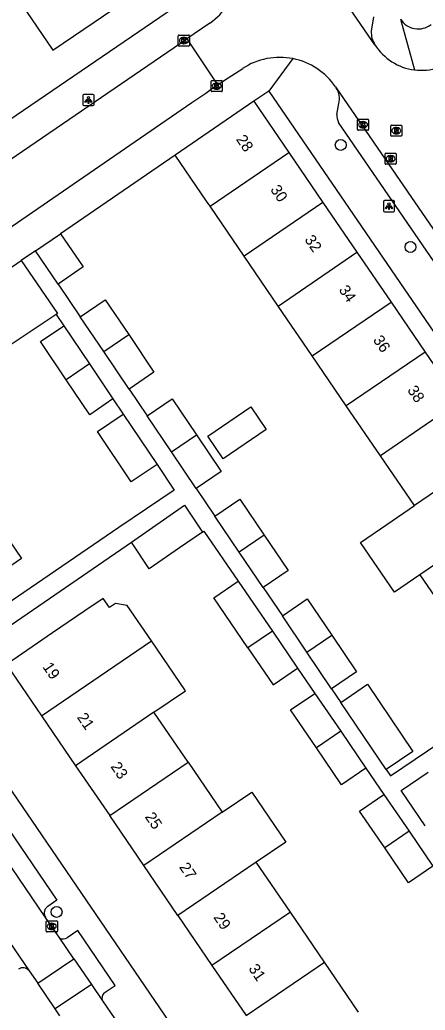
# Model space of a CAD drawing. Extents: x 157466 to 158888, y 383063 to 384677.
# Drawn here: x 158228.2 to 158264.6, y 383822.7 to 383911.7 of the extents above; entities that cross this region are included whole.
import ezdxf

# ---------------------------------------------------------------- set-up
doc = ezdxf.new("R2010")
doc.units = 0
for name, color, linetype in [('IMGEO_Boom', 7, 'Continuous'), ('IMGEO_Kolk', 7, 'Continuous'), ('IMGEO_Lichtpunt', 7, 'Continuous'), ('IMGEO_Muur', 7, 'Continuous'), ('IMGEO_Pand', 7, 'Continuous'), ('IMGEO_Pand_nummerreeks', 7, 'Continuous'), ('IMGEO_Rijbaan_lokaal_open', 7, 'Continuous'), ('IMGEO_Rioolput', 7, 'Continuous'), ('IMGEO_Voetpad_open', 7, 'Continuous')]:
    doc.layers.add(name, color=color, linetype=linetype)

msp = doc.modelspace()

# ---------------------------------------------------------------- linework, layer by layer
at = {"layer": 'IMGEO_Boom'}
for centre in [(158257.057, 383900.449), (158263.312, 383891.278), (158231.547, 383831.557)]:
    msp.add_circle(centre, 0.489, dxfattribs=at)
at = {"layer": 'IMGEO_Kolk'}
for p, q in [((158242.465, 383909.389), (158242.465, 383910.241)), ((158242.54, 383910.315), (158243.392, 383910.315)), ((158242.953, 383910.095), (158242.978, 383910.095)), ((158243.466, 383910.241), (158243.466, 383909.389)), ((158243.392, 383909.315), (158242.54, 383909.315)), ((158242.976, 383909.535), (158242.951, 383909.535)), ((158245.42, 383905.308), (158245.42, 383906.16)), ((158245.495, 383906.234), (158246.347, 383906.234)), ((158246.421, 383906.16), (158246.421, 383905.308)), ((158246.347, 383905.234), (158245.495, 383905.234)), ((158245.931, 383905.454), (158245.906, 383905.454)), ((158245.908, 383906.014), (158245.933, 383906.014)), ((158258.559, 383901.837), (158258.559, 383902.689)), ((158258.634, 383902.763), (158259.486, 383902.763)), ((158259.047, 383902.543), (158259.072, 383902.543)), ((158259.56, 383902.689), (158259.56, 383901.837)), ((158259.486, 383901.763), (158258.634, 383901.763)), ((158259.07, 383901.983), (158259.045, 383901.983)), ((158230.613, 383829.835), (158230.613, 383830.687)), ((158230.688, 383830.761), (158231.54, 383830.761)), ((158231.101, 383830.541), (158231.126, 383830.541)), ((158231.614, 383830.687), (158231.614, 383829.835)), ((158231.54, 383829.761), (158230.688, 383829.761)), ((158231.124, 383829.981), (158231.099, 383829.981))]:
    msp.add_line(p, q, dxfattribs=at)
for points in [[(158242.465, 383909.389), (158242.465, 383910.241)], [(158242.54, 383910.315), (158243.392, 383910.315)], [(158242.786, 383910.015), (158242.909, 383910.015), (158242.909, 383909.864), (158243.039, 383910.015), (158243.203, 383910.015), (158243.057, 383909.864), (158243.21, 383909.615), (158243.058, 383909.615), (158242.973, 383909.779), (158242.909, 383909.712), (158242.909, 383909.615), (158242.786, 383909.615), (158242.786, 383910.015)], [(158243.466, 383910.241), (158243.466, 383909.389)], [(158243.392, 383909.315), (158242.54, 383909.315)], [(158245.42, 383905.308), (158245.42, 383906.16)], [(158245.495, 383906.234), (158246.347, 383906.234)], [(158246.421, 383906.16), (158246.421, 383905.308)], [(158246.347, 383905.234), (158245.495, 383905.234)], [(158245.741, 383905.934), (158245.864, 383905.934), (158245.864, 383905.783), (158245.994, 383905.934), (158246.158, 383905.934), (158246.012, 383905.783), (158246.165, 383905.534), (158246.013, 383905.534), (158245.928, 383905.698), (158245.864, 383905.631), (158245.864, 383905.534), (158245.741, 383905.534), (158245.741, 383905.934)], [(158258.559, 383901.837), (158258.559, 383902.689)], [(158258.634, 383902.763), (158259.486, 383902.763)], [(158259.56, 383902.689), (158259.56, 383901.837)], [(158259.486, 383901.763), (158258.634, 383901.763)], [(158258.88, 383902.463), (158259.003, 383902.463), (158259.003, 383902.312), (158259.133, 383902.463), (158259.297, 383902.463), (158259.151, 383902.312), (158259.304, 383902.063), (158259.152, 383902.063), (158259.067, 383902.227), (158259.003, 383902.16), (158259.003, 383902.063), (158258.88, 383902.063), (158258.88, 383902.463)], [(158230.613, 383829.835), (158230.613, 383830.687)], [(158230.688, 383830.761), (158231.54, 383830.761)], [(158230.934, 383830.461), (158231.057, 383830.461), (158231.057, 383830.31), (158231.187, 383830.461), (158231.351, 383830.461), (158231.205, 383830.31), (158231.358, 383830.061), (158231.206, 383830.061), (158231.121, 383830.225), (158231.057, 383830.158), (158231.057, 383830.061), (158230.934, 383830.061), (158230.934, 383830.461)], [(158231.614, 383830.687), (158231.614, 383829.835)], [(158231.54, 383829.761), (158230.688, 383829.761)]]:
    msp.add_lwpolyline(points, dxfattribs=at)
for centre, start, end in [((158242.542, 383910.239), 91.55205, 178.44795), ((158242.542, 383910.239), 91.55205, 178.44795), ((158243.39, 383910.239), 1.55205, 88.44795), ((158243.39, 383910.239), 1.55205, 88.44795), ((158242.542, 383909.391), 181.55205, 268.44795), ((158242.542, 383909.391), 181.55205, 268.44795), ((158243.39, 383909.391), 271.55205, 358.44795), ((158243.39, 383909.391), 271.55205, 358.44795), ((158245.497, 383906.158), 91.55205, 178.44795), ((158245.497, 383906.158), 91.55205, 178.44795), ((158246.345, 383906.158), 1.55205, 88.44795), ((158246.345, 383906.158), 1.55205, 88.44795), ((158245.497, 383905.31), 181.55205, 268.44795), ((158245.497, 383905.31), 181.55205, 268.44795), ((158246.345, 383905.31), 271.55205, 358.44795), ((158246.345, 383905.31), 271.55205, 358.44795), ((158258.636, 383902.687), 91.55205, 178.44795), ((158258.636, 383902.687), 91.55205, 178.44795), ((158259.484, 383902.687), 1.55205, 88.44795), ((158259.484, 383902.687), 1.55205, 88.44795), ((158258.636, 383901.839), 181.55205, 268.44795), ((158258.636, 383901.839), 181.55205, 268.44795), ((158259.484, 383901.839), 271.55205, 358.44795), ((158259.484, 383901.839), 271.55205, 358.44795), ((158230.69, 383830.685), 91.55205, 178.44795), ((158230.69, 383830.685), 91.55205, 178.44795), ((158231.538, 383830.685), 1.55205, 88.44795), ((158231.538, 383830.685), 1.55205, 88.44795), ((158230.69, 383829.837), 181.55205, 268.44795), ((158230.69, 383829.837), 181.55205, 268.44795), ((158231.538, 383829.837), 271.55205, 358.44795), ((158231.538, 383829.837), 271.55205, 358.44795)]:
    msp.add_arc(centre, 0.0765, start, end, dxfattribs=at)
for centre, major_axis, ratio, start_param, end_param in [((158242.952, 383909.815), (-0.387, 0.002), 0.722429, 4.712389, 7.853982), ((158242.977, 383909.815), (-0.39, 0.002), 0.717154, 1.570796, 4.712389), ((158245.907, 383905.734), (-0.387, 0.002), 0.722429, 4.712389, 7.853982), ((158245.932, 383905.734), (-0.39, 0.002), 0.717154, 1.570796, 4.712389), ((158259.046, 383902.263), (-0.387, 0.002), 0.722429, 4.712389, 7.853982), ((158259.071, 383902.263), (-0.39, 0.002), 0.717154, 1.570796, 4.712389), ((158231.1, 383830.261), (-0.387, 0.002), 0.722429, 4.712389, 7.853982), ((158231.125, 383830.261), (-0.39, 0.002), 0.717154, 1.570796, 4.712389)]:
    msp.add_ellipse(centre, major_axis=major_axis, ratio=ratio, start_param=start_param, end_param=end_param, dxfattribs=at)
at = {"layer": 'IMGEO_Lichtpunt'}
for p, q in [((158233.909, 383904.886), (158233.909, 383904.079)), ((158233.909, 383904.886), (158233.909, 383904.079)), ((158234.811, 383904.981), (158234.003, 383904.981)), ((158234.811, 383904.981), (158234.003, 383904.981)), ((158234.905, 383904.079), (158234.905, 383904.886)), ((158234.905, 383904.079), (158234.905, 383904.886)), ((158234.003, 383903.985), (158234.811, 383903.985)), ((158234.003, 383903.985), (158234.811, 383903.985)), ((158261.786, 383895.442), (158260.978, 383895.442)), ((158261.786, 383895.442), (158260.978, 383895.442)), ((158260.884, 383895.347), (158260.884, 383894.54)), ((158260.884, 383895.347), (158260.884, 383894.54)), ((158261.88, 383894.54), (158261.88, 383895.347)), ((158261.88, 383894.54), (158261.88, 383895.347)), ((158260.978, 383894.446), (158261.786, 383894.446)), ((158260.978, 383894.446), (158261.786, 383894.446))]:
    msp.add_line(p, q, dxfattribs=at)
for points in [[(158234.283, 383904.55), (158234.322, 383904.522), (158234.134, 383904.26), (158234.096, 383904.287), (158234.283, 383904.55)], [(158234.385, 383904.502), (158234.432, 383904.502), (158234.432, 383904.18), (158234.385, 383904.18), (158234.385, 383904.502)], [(158234.495, 383904.522), (158234.533, 383904.549), (158234.72, 383904.287), (158234.681, 383904.259), (158234.495, 383904.522)], [(158261.258, 383895.011), (158261.297, 383894.983), (158261.109, 383894.721), (158261.071, 383894.748), (158261.258, 383895.011)], [(158261.36, 383894.963), (158261.407, 383894.963), (158261.407, 383894.641), (158261.36, 383894.641), (158261.36, 383894.963)], [(158261.47, 383894.983), (158261.508, 383895.01), (158261.695, 383894.748), (158261.656, 383894.72), (158261.47, 383894.983)]]:
    msp.add_lwpolyline(points, dxfattribs=at)
for centre in [(158234.408, 383904.684), (158261.383, 383895.145)]:
    msp.add_circle(centre, 0.0994, dxfattribs=at)
for centre, start, end in [((158234.003, 383904.886), 90, 180), ((158234.003, 383904.886), 90, 180), ((158234.811, 383904.886), 0, 90), ((158234.811, 383904.886), 0, 90), ((158234.003, 383904.079), 180, 270), ((158234.003, 383904.079), 180, 270), ((158234.811, 383904.079), 270, 0), ((158234.811, 383904.079), 270, 360), ((158260.978, 383895.347), 90, 180), ((158260.978, 383895.347), 90, 180), ((158261.786, 383895.347), 0, 90), ((158261.786, 383895.347), 0, 90), ((158260.978, 383894.54), 180, 270), ((158260.978, 383894.54), 180, 270), ((158261.786, 383894.54), 270, 0), ((158261.786, 383894.54), 270, 360)]:
    msp.add_arc(centre, 0.0946, start, end, dxfattribs=at)
at = {"layer": 'IMGEO_Muur'}
msp.add_lwpolyline([(158225.999, 383901.836), (158240.803, 383911.908)], dxfattribs=at)
at = {"layer": 'IMGEO_Pand'}
for points in [[(158230.286, 383915.828), (158227.724, 383914.08), (158228.397, 383913.094), (158231.215, 383908.963), (158239.475, 383914.599), (158235.983, 383919.716)], [(158249.254, 383904.367), (158242.18, 383899.539)], [(158249.254, 383904.367), (158252.397, 383899.761)], [(158245.323, 383894.934), (158244.999, 383895.409), (158242.18, 383899.539)], [(158245.323, 383894.934), (158252.397, 383899.761)], [(158252.397, 383899.761), (158255.454, 383895.281)], [(158248.38, 383890.454), (158245.323, 383894.934)], [(158255.454, 383895.281), (158248.38, 383890.454)], [(158255.454, 383895.281), (158258.512, 383890.8)], [(158229.648, 383890.924), (158231.893, 383892.465)], [(158231.893, 383892.465), (158233.935, 383889.491), (158231.689, 383887.95)], [(158223.608, 383886.804), (158228.373, 383890.075)], [(158228.373, 383890.075), (158231.64, 383885.314), (158231.509, 383885.226)], [(158231.689, 383887.95), (158229.648, 383890.924)], [(158251.438, 383885.973), (158248.38, 383890.454)], [(158251.438, 383885.973), (158258.512, 383890.8)], [(158258.512, 383890.8), (158261.569, 383886.32)], [(158231.509, 383885.226), (158226.841, 383882.092), (158225.794, 383883.618), (158223.608, 383886.804)], [(158233.67, 383885.007), (158235.914, 383886.521), (158238.017, 383883.406)], [(158254.495, 383881.493), (158251.438, 383885.973)], [(158254.495, 383881.493), (158261.569, 383886.32)], [(158261.569, 383886.32), (158264.626, 383881.84)], [(158235.781, 383881.88), (158233.67, 383885.007)], [(158232.4, 383879.357), (158230.095, 383882.79), (158232.197, 383884.201)], [(158232.197, 383884.201), (158234.492, 383880.783)], [(158235.781, 383881.88), (158238.017, 383883.406)], [(158238.017, 383883.406), (158240.288, 383880.044), (158238.052, 383878.518)], [(158238.052, 383878.518), (158235.781, 383881.88)], [(158257.552, 383877.012), (158254.495, 383881.493)], [(158264.626, 383881.84), (158257.552, 383877.012)], [(158264.626, 383881.84), (158267.683, 383877.36)], [(158234.492, 383880.783), (158232.4, 383879.357)], [(158234.492, 383880.783), (158236.608, 383877.632)], [(158236.608, 383877.632), (158234.516, 383876.206), (158232.4, 383879.357)], [(158239.672, 383876.119), (158241.907, 383877.645), (158244.095, 383874.406)], [(158246.501, 383872.248), (158245.109, 383874.287), (158248.973, 383876.924), (158250.365, 383874.885), (158246.501, 383872.248)], [(158260.609, 383872.533), (158257.552, 383877.012)], [(158267.683, 383877.36), (158260.609, 383872.533)], [(158240.561, 383871.744), (158238.249, 383870.192), (158235.226, 383874.695), (158237.527, 383876.263)], [(158237.527, 383876.263), (158240.561, 383871.744)], [(158241.859, 383872.881), (158239.672, 383876.119)], [(158241.859, 383872.881), (158244.095, 383874.406)], [(158244.095, 383874.406), (158246.309, 383871.127), (158244.074, 383869.602)], [(158244.074, 383869.602), (158241.859, 383872.881)], [(158263.666, 383868.053), (158260.609, 383872.533)], [(158270.74, 383872.88), (158263.666, 383868.053)], [(158238.26, 383864.78), (158243.036, 383868.088), (158244.636, 383865.669)], [(158245.755, 383867.113), (158247.99, 383868.638), (158250.172, 383865.406)], [(158264.167, 383861.827), (158261.875, 383860.263), (158258.817, 383864.744), (158261.188, 383866.362), (158263.666, 383868.053)], [(158273.798, 383868.399), (158264.167, 383861.827)], [(158225.327, 383867.785), (158228.385, 383863.3), (158225.487, 383861.324), (158221.356, 383858.507), (158218.297, 383862.992)], [(158247.937, 383863.881), (158245.755, 383867.113)], [(158244.636, 383865.669), (158242.591, 383864.253), (158239.861, 383862.362), (158238.26, 383864.78)], [(158250.172, 383865.406), (158247.937, 383863.881)], [(158250.172, 383865.406), (158252.33, 383862.21), (158250.095, 383860.685)], [(158250.095, 383860.685), (158247.937, 383863.881)], [(158264.167, 383861.827), (158267.224, 383857.347), (158269.781, 383859.092)], [(158248.728, 383855.27), (158245.66, 383859.761), (158247.847, 383861.253)], [(158247.847, 383861.253), (158250.916, 383856.762)], [(158240.051, 383855.907), (158237.882, 383859.087), (158236.849, 383859.271), (158236.297, 383858.895), (158235.733, 383859.721), (158234.081, 383858.594), (158231.175, 383856.612), (158227.044, 383853.795), (158230.19, 383849.182)], [(158251.813, 383858.141), (158254.048, 383859.666), (158256.249, 383856.407)], [(158254.015, 383854.882), (158251.813, 383858.141)], [(158250.916, 383856.762), (158248.728, 383855.27)], [(158250.916, 383856.762), (158253.179, 383853.45)], [(158254.015, 383854.882), (158256.249, 383856.407)], [(158256.249, 383856.407), (158258.471, 383853.116), (158256.237, 383851.592)], [(158230.19, 383849.182), (158240.051, 383855.907)], [(158240.288, 383849.493), (158243.112, 383851.419), (158240.051, 383855.907)], [(158248.728, 383855.27), (158250.991, 383851.958), (158253.179, 383853.45)], [(158256.237, 383851.592), (158254.015, 383854.882)], [(158257.054, 383850.382), (158259.458, 383852.022), (158263.537, 383845.982), (158261.125, 383844.354)], [(158254.864, 383846.29), (158252.536, 383849.696), (158254.724, 383851.189)], [(158254.724, 383851.189), (158257.052, 383847.782)], [(158261.125, 383844.354), (158257.054, 383850.382)], [(158230.19, 383849.182), (158233.251, 383844.694)], [(158240.288, 383849.493), (158233.251, 383844.694)], [(158243.349, 383845.004), (158240.288, 383849.493)], [(158257.052, 383847.782), (158254.864, 383846.29)], [(158257.052, 383847.782), (158259.321, 383844.463)], [(158259.321, 383844.463), (158257.132, 383842.97), (158254.864, 383846.29)], [(158233.251, 383844.694), (158236.312, 383840.206)], [(158236.312, 383840.206), (158243.349, 383845.004)], [(158243.349, 383845.004), (158246.411, 383840.515)], [(158264.642, 383839.288), (158262.478, 383842.453), (158264.887, 383844.101)], [(158246.411, 383840.515), (158249.066, 383842.326), (158252.127, 383837.837), (158249.472, 383836.027)], [(158261, 383837.308), (158258.739, 383840.618), (158260.928, 383842.111)], [(158260.928, 383842.111), (158263.189, 383838.801)], [(158246.411, 383840.515), (158239.373, 383835.717)], [(158239.373, 383835.717), (158236.312, 383840.206)], [(158263.189, 383838.801), (158261, 383837.308)], [(158263.189, 383838.801), (158265.327, 383835.672)], [(158265.327, 383835.672), (158263.138, 383834.179), (158261, 383837.308)], [(158249.472, 383836.027), (158242.434, 383831.228)], [(158252.532, 383831.539), (158249.472, 383836.027)], [(158242.434, 383831.228), (158239.373, 383835.717)], [(158252.532, 383831.539), (158245.495, 383826.74)], [(158255.594, 383827.05), (158252.532, 383831.539)], [(158242.434, 383831.228), (158245.495, 383826.74)], [(158248.556, 383822.251), (158255.594, 383827.05)], [(158258.655, 383822.561), (158255.594, 383827.05)], [(158245.495, 383826.74), (158248.556, 383822.251)]]:
    msp.add_lwpolyline(points, dxfattribs=at)
at = {"layer": 'IMGEO_Rijbaan_lokaal_open'}
for points in [[(158260.125, 383909.444), (158249.98, 383924.228)], [(158245.288, 383911.384), (158243.23, 383909.982)], [(158202.489, 383882.225), (158214.323, 383890.192), (158220.295, 383894.284), (158227.34, 383899.111), (158243.23, 383909.982)], [(158243.23, 383909.982), (158246, 383905.83)], [(158246, 383905.83), (158246.955, 383906.46), (158248.25, 383907.313)], [(158246, 383905.83), (158244.954, 383905.077), (158243.701, 383904.239), (158224.74, 383891.195), (158221.792, 383889.169), (158213.929, 383883.767), (158205.233, 383877.954)], [(158256.59, 383905.67), (158256.656, 383905.574)], [(158256.656, 383905.574), (158266.381, 383891.427)], [(158200.985, 383867.438), (158229.086, 383826.263)], [(158230.56, 383831.07), (158220.309, 383846.103)], [(158231.833, 383829.207), (158231.501, 383829.694), (158230.56, 383831.07)], [(158233.106, 383827.345), (158231.833, 383829.207)], [(158229.849, 383825.146), (158233.106, 383827.345)], [(158233.106, 383827.345), (158234.672, 383825.051)], [(158229.086, 383826.263), (158229.849, 383825.146)], [(158231.411, 383822.857), (158229.849, 383825.146)], [(158234.672, 383825.051), (158231.411, 383822.857)], [(158234.672, 383825.051), (158235.678, 383823.579)], [(158235.678, 383823.579), (158236.772, 383821.968), (158237.215, 383821.317)], [(158231.849, 383822.216), (158231.411, 383822.857)]]:
    msp.add_lwpolyline(points, dxfattribs=at)
for centre, radius, start, end in [((158241.748, 383916.483), 6.208, 304.77086, 348.05031), ((158264.269, 383912.035), 4.887, 212.01533, 262.91256), ((158251.58, 383902.242), 6.067, 78.8372, 123.29308), ((158251.578, 383902.231), 6.078, 34.45961, 78.83867), ((158264.268, 383912.037), 4.89, 262.92843, 313.81208)]:
    msp.add_arc(centre, radius, start, end, dxfattribs=at)
at = {"layer": 'IMGEO_Rioolput'}
for p, q in [((158261.54, 383901.301), (158261.54, 383902.153)), ((158261.615, 383902.227), (158262.467, 383902.227)), ((158262.028, 383902.007), (158262.053, 383902.007)), ((158262.541, 383902.153), (158262.541, 383901.301)), ((158262.467, 383901.227), (158261.615, 383901.227)), ((158262.051, 383901.447), (158262.026, 383901.447)), ((158261.033, 383898.785), (158261.033, 383899.637)), ((158261.108, 383899.711), (158261.96, 383899.711)), ((158261.521, 383899.491), (158261.546, 383899.491)), ((158262.034, 383899.637), (158262.034, 383898.785)), ((158261.96, 383898.711), (158261.108, 383898.711)), ((158261.544, 383898.931), (158261.519, 383898.931))]:
    msp.add_line(p, q, dxfattribs=at)
for points in [[(158261.54, 383901.301), (158261.54, 383902.153)], [(158261.615, 383902.227), (158262.467, 383902.227)], [(158262.129, 383901.925), (158261.877, 383901.927), (158261.877, 383901.527)], [(158261.877, 383901.527), (158262.001, 383901.527), (158262.001, 383901.689), (158262.012, 383901.689)], [(158262.055, 383901.846), (158262.001, 383901.846), (158262.001, 383901.765)], [(158262.001, 383901.765), (158262.053, 383901.765)], [(158262.059, 383901.66), (158262.13, 383901.527), (158262.27, 383901.527), (158262.205, 383901.653)], [(158262.541, 383902.153), (158262.541, 383901.301)], [(158262.467, 383901.227), (158261.615, 383901.227)], [(158261.033, 383898.785), (158261.033, 383899.637)], [(158261.108, 383899.711), (158261.96, 383899.711)], [(158261.622, 383899.409), (158261.37, 383899.411), (158261.37, 383899.011)], [(158261.37, 383899.011), (158261.494, 383899.011), (158261.494, 383899.173), (158261.505, 383899.173)], [(158261.548, 383899.33), (158261.494, 383899.33), (158261.494, 383899.249)], [(158261.494, 383899.249), (158261.546, 383899.249)], [(158261.552, 383899.144), (158261.623, 383899.011), (158261.763, 383899.011), (158261.698, 383899.137)], [(158262.034, 383899.637), (158262.034, 383898.785)], [(158261.96, 383898.711), (158261.108, 383898.711)]]:
    msp.add_lwpolyline(points, dxfattribs=at)
for centre, radius, start, end in [((158261.617, 383902.151), 0.0765, 91.55205, 178.44795), ((158261.617, 383902.151), 0.0765, 91.55205, 178.44795), ((158262.011, 383901.636), 0.0533, 26.02933, 88.69889), ((158262.037, 383901.954), 0.19, 274.7715, 282.96867), ((158262.061, 383901.75), 0.0964, 77.00612, 93.18647), ((158262.075, 383901.807), 0.0378, 276.66336, 79.67722), ((158262.128, 383901.815), 0.109, 350.36119, 89.41601), ((158262.126, 383901.815), 0.112, 277.58423, 350.98172), ((158262.11, 383901.6), 0.108, 29.51342, 73.79051), ((158262.465, 383902.151), 0.0765, 1.55205, 88.44795), ((158262.465, 383902.151), 0.0765, 1.55205, 88.44795), ((158261.617, 383901.303), 0.0765, 181.55205, 268.44795), ((158261.617, 383901.303), 0.0765, 181.55205, 268.44795), ((158262.465, 383901.303), 0.0765, 271.55205, 358.44795), ((158262.465, 383901.303), 0.0765, 271.55205, 358.44795), ((158261.11, 383899.635), 0.0765, 91.55205, 178.44795), ((158261.11, 383899.635), 0.0765, 91.55205, 178.44795), ((158261.504, 383899.12), 0.0533, 26.02933, 88.69889), ((158261.53, 383899.438), 0.19, 274.7715, 282.96867), ((158261.554, 383899.234), 0.0964, 77.00612, 93.18647), ((158261.568, 383899.291), 0.0378, 276.66336, 79.67722), ((158261.621, 383899.299), 0.109, 350.36119, 89.41601), ((158261.619, 383899.299), 0.112, 277.58423, 350.98172), ((158261.603, 383899.084), 0.108, 29.51342, 73.79051), ((158261.958, 383899.635), 0.0765, 1.55205, 88.44795), ((158261.958, 383899.635), 0.0765, 1.55205, 88.44795), ((158261.11, 383898.787), 0.0765, 181.55205, 268.44795), ((158261.11, 383898.787), 0.0765, 181.55205, 268.44795), ((158261.958, 383898.787), 0.0765, 271.55205, 358.44795), ((158261.958, 383898.787), 0.0765, 271.55205, 358.44795)]:
    msp.add_arc(centre, radius, start, end, dxfattribs=at)
for centre, major_axis, ratio, start_param, end_param in [((158262.027, 383901.727), (-0.387, 0.002), 0.722429, 4.712389, 7.853982), ((158262.052, 383901.727), (-0.39, 0.002), 0.717154, 1.570796, 4.712389), ((158261.52, 383899.211), (-0.387, 0.002), 0.722429, 4.712389, 7.853982), ((158261.545, 383899.211), (-0.39, 0.002), 0.717154, 1.570796, 4.712389)]:
    msp.add_ellipse(centre, major_axis=major_axis, ratio=ratio, start_param=start_param, end_param=end_param, dxfattribs=at)
at = {"layer": 'IMGEO_Voetpad_open'}
for points in [[(158225.416, 383901.438), (158225.999, 383901.836), (158240.803, 383911.908), (158243.26, 383913.632)], [(158259.992, 383911.954), (158259.797, 383910.671)], [(158262.42, 383911.739), (158263.666, 383907.185)], [(158252.755, 383908.194), (158250.603, 383905.26)], [(158250.603, 383905.26), (158249.254, 383904.367)], [(158250.603, 383905.26), (158282.821, 383858.177)], [(158256.705, 383903.181), (158256.886, 383904.168)], [(158315.648, 383818.052), (158314.799, 383818.227), (158314.179, 383818.673), (158308.868, 383826.633), (158286.012, 383859.903), (158283.979, 383862.899), (158256.861, 383902.472)], [(158242.18, 383899.539), (158231.893, 383892.465)], [(158229.648, 383890.924), (158228.373, 383890.075)], [(158231.689, 383887.95), (158233.67, 383885.007)], [(158231.509, 383885.226), (158232.197, 383884.201)], [(158238.052, 383878.518), (158239.672, 383876.119)], [(158236.608, 383877.632), (158237.527, 383876.263)], [(158240.561, 383871.744), (158242.115, 383869.429), (158237.141, 383866.09), (158219.571, 383854.073)], [(158244.074, 383869.602), (158245.755, 383867.113)], [(158244.636, 383865.669), (158244.767, 383865.76), (158247.847, 383861.253)], [(158220.561, 383852.622), (158238.26, 383864.78)], [(158250.095, 383860.685), (158251.813, 383858.141)], [(158261.125, 383844.354), (158261.51, 383843.785), (158282.821, 383858.177)], [(158253.179, 383853.45), (158254.724, 383851.189)], [(158254.415, 383802.985), (158220.561, 383852.622)], [(158256.237, 383851.592), (158257.054, 383850.382)], [(158222.289, 383846.241), (158231.582, 383832.612), (158230.745, 383832.042), (158230.695, 383832.005), (158230.648, 383831.964), (158230.606, 383831.918), (158230.567, 383831.869), (158230.533, 383831.817), (158230.504, 383831.762), (158230.48, 383831.704), (158230.461, 383831.645), (158230.448, 383831.584), (158230.44, 383831.522), (158230.438, 383831.46), (158230.441, 383831.398), (158230.45, 383831.336), (158230.464, 383831.276), (158230.483, 383831.216), (158230.508, 383831.159), (158230.538, 383831.105), (158230.56, 383831.07)], [(158259.321, 383844.463), (158260.928, 383842.111)], [(158235.823, 383824.282), (158236.799, 383824.964), (158233.445, 383829.881), (158232.5, 383829.24)]]:
    msp.add_lwpolyline(points, dxfattribs=at)
for centre, radius, start, end in [((158264.005, 383912.734), 1.871, 212.10654, 308.10184), ((158261.72, 383910.528), 1.928, 175.73739, 214.19518), ((158255.163, 383904.608), 1.778, 345.6704, 32.91044), ((158257.943, 383903.082), 1.242, 175.41347, 209.40445), ((158232.14, 383829.752), 0.625, 240.56053, 305.1043), ((158228.526, 383825.844), 0.699, 36.80506, 124.40652), ((158236.167, 383823.845), 0.556, 128.1835, 208.50784)]:
    msp.add_arc(centre, radius, start, end, dxfattribs=at)

# ---------------------------------------------------------------- texts
at = {"layer": 'IMGEO_Pand_nummerreeks'}
for s, rotation, p in [('28', 304.30866, (158247.618, 383900.946)), ('30', 304.30866, (158250.692, 383896.441)), ('32', 304.30866, (158253.763, 383891.941)), ('34', 304.30866, (158256.838, 383887.433)), ('36', 304.30866, (158259.912, 383882.928)), ('38', 304.30866, (158262.988, 383878.421)), ('19', 304.29131, (158230.251, 383853.565)), ('21', 304.29131, (158233.341, 383849.034)), ('23', 304.29337, (158236.355, 383844.614)), ('25', 304.29337, (158239.433, 383840.1)), ('27', 304.29131, (158242.511, 383835.587)), ('29', 304.29337, (158245.589, 383831.074)), ('31', 304.29131, (158248.731, 383826.467))]:
    msp.add_text(s, height=1, rotation=rotation, dxfattribs=at).set_placement(p)

doc.saveas('drawing.dxf')
